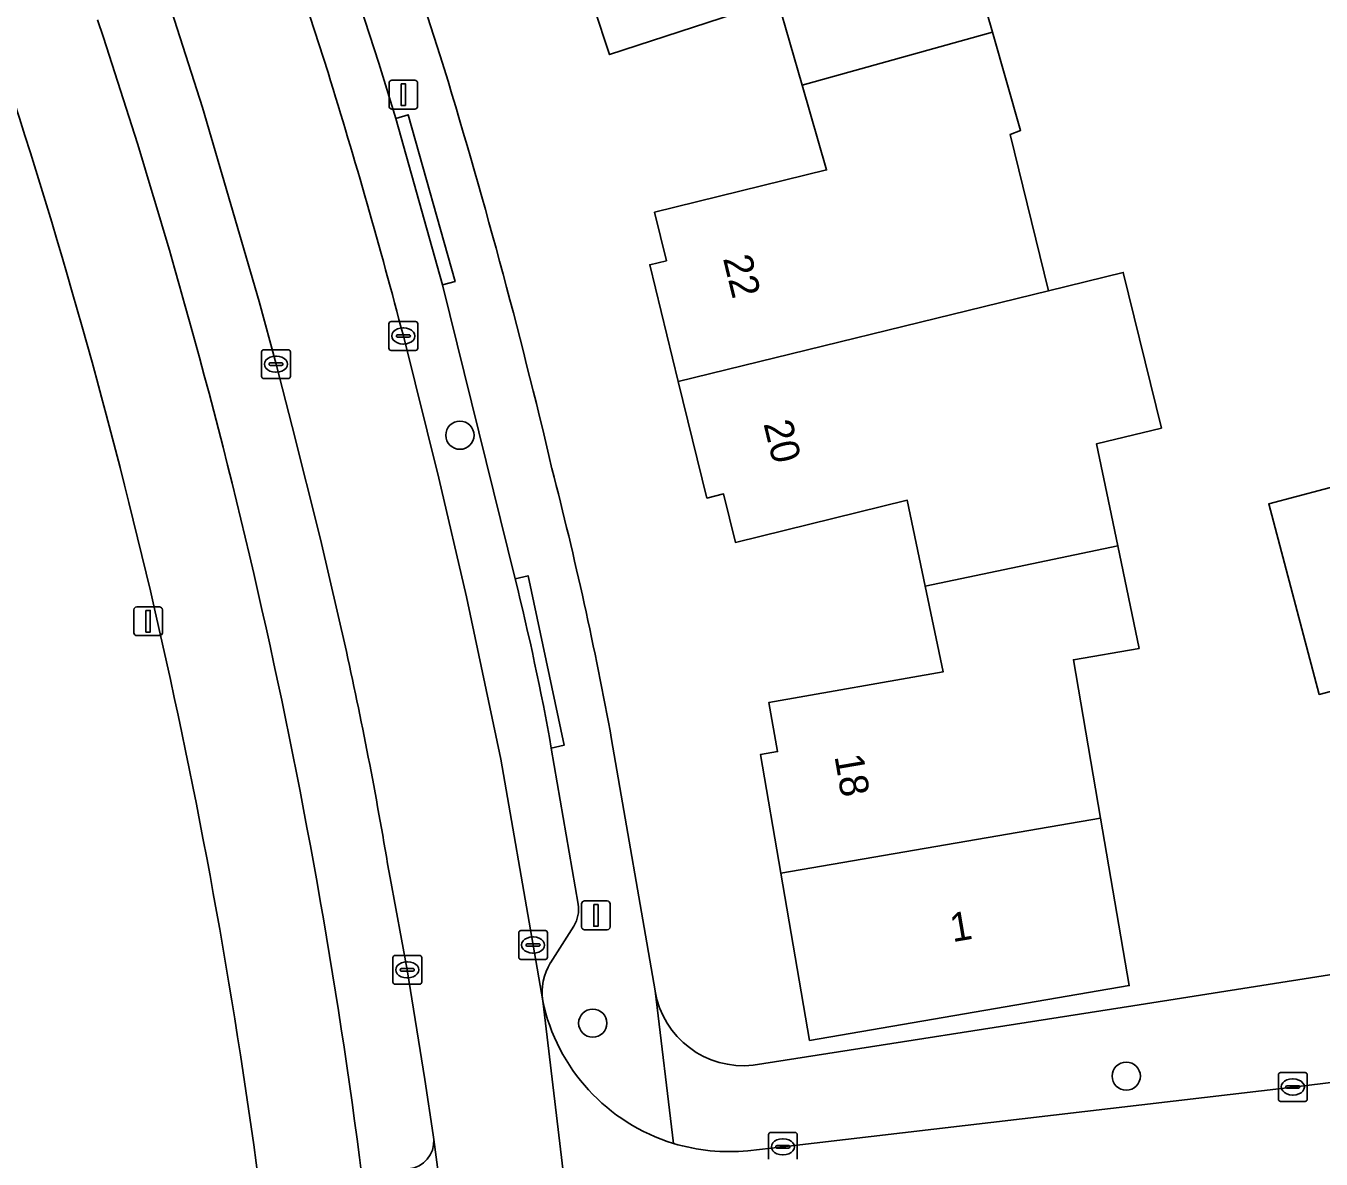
# Model space of a CAD drawing. Extents: x 162879 to 165540, y 384011 to 385181.
# Drawn here: x 163777.66 to 163822.64, y 384375.35 to 384414.7 of the extents above; entities that cross this region are included whole.
import ezdxf

# ---------------------------------------------------------------- set-up
doc = ezdxf.new("R2010")
doc.units = 0
for name, color, linetype in [('IMGEO_Boom', 7, 'Continuous'), ('IMGEO_Erf', 7, 'Continuous'), ('IMGEO_Fietspad_gesloten', 7, 'Continuous'), ('IMGEO_Groenvoorziening', 7, 'Continuous'), ('IMGEO_Kolk', 7, 'Continuous'), ('IMGEO_Lichtmast', 7, 'Continuous'), ('IMGEO_Muur', 7, 'Continuous'), ('IMGEO_Pand', 7, 'Continuous'), ('IMGEO_Pand_nummerreeks', 7, 'Continuous'), ('IMGEO_Parkeervlak_open', 7, 'Continuous'), ('IMGEO_Rijbaan_lokaal_open', 7, 'Continuous'), ('IMGEO_Voetpad_open', 7, 'Continuous')]:
    doc.layers.add(name, color=color, linetype=linetype)

msp = doc.modelspace()

# ---------------------------------------------------------------- linework, layer by layer
at = {"layer": 'IMGEO_Boom'}
for centre in [(163792.734, 384400.485), (163797.345, 384380.069), (163815.873, 384378.229)]:
    msp.add_circle(centre, 0.489, dxfattribs=at)
at = {"layer": 'IMGEO_Erf'}
for points in [[(163788.875, 384423.518), (163792.049, 384413.663)], [(163810.195, 384418.068), (163811.223, 384414.483), (163812.202, 384411.07), (163811.837, 384410.925), (163813.167, 384405.499), (163815.77, 384406.136), (163817.093, 384400.732), (163814.837, 384400.18), (163815.298, 384397.976), (163815.575, 384396.648), (163816.319, 384393.081), (163814.036, 384392.69), (163814.979, 384387.19), (163815.976, 384381.375), (163804.874, 384379.47), (163803.877, 384385.278), (163803.171, 384389.395), (163803.763, 384389.497), (163803.464, 384391.204), (163809.512, 384392.264), (163808.89, 384395.245), (163808.267, 384398.227), (163802.303, 384396.764), (163801.891, 384398.445), (163801.309, 384398.303), (163800.316, 384402.352), (163799.323, 384406.403), (163799.905, 384406.545), (163799.492, 384408.228), (163805.465, 384409.694), (163804.622, 384412.635), (163803.766, 384415.619), (163797.929, 384413.701), (163797.388, 384415.352)], [(163825.485, 384392.258), (163822.572, 384391.486), (163820.82, 384398.098), (163823.706, 384398.863)], [(163802.92, 384378.611), (163816.096, 384380.674), (163825.065, 384382.078), (163825.148, 384382.091), (163865.727, 384392.809)], [(163798.001, 384389.923), (163799.512, 384381.186)]]:
    msp.add_lwpolyline(points, dxfattribs=at)
for centre, radius, start, end in [((163583.354, 384349.501), 218.336, 13.19052, 17.08969), ((163667.151, 384366.009), 133.017, 10.35715, 14.5042), ((163802.573, 384381.694), 3.103, 189.4288, 276.4236)]:
    msp.add_arc(centre, radius, start, end, dxfattribs=at)
at = {"layer": 'IMGEO_Fietspad_gesloten'}
msp.add_lwpolyline([(163792.338, 384372.171), (163791.826, 384376.032)], dxfattribs=at)
for centre, radius, start, end in [((163578.641, 384347.699), 212.423, 7.31878, 18.44587), ((163573.957, 384346.303), 213.668, 7.60789, 18.44351), ((163790.862, 384375.972), 0.966, 275.5515, 3.5699)]:
    msp.add_arc(centre, radius, start, end, dxfattribs=at)
at = {"layer": 'IMGEO_Groenvoorziening'}
for points in [[(163788.792, 384392.978), (163787.888, 384396.88), (163786.914, 384400.782), (163786.348, 384402.953), (163785.764, 384405.127), (163783.795, 384411.861), (163780.97, 384420.679), (163779.798, 384424.262), (163779.007, 384426.681)], [(163791.826, 384376.032), (163791.802, 384376.197), (163791.512, 384378.112), (163790.907, 384381.92), (163790.306, 384385.111)]]:
    msp.add_lwpolyline(points, dxfattribs=at)
for centre, radius, start, end in [((163578.641, 384347.699), 212.423, 7.31878, 18.44587), ((163573.957, 384346.303), 213.668, 7.60789, 18.44351), ((163637.71, 384359.823), 154.677, 9.4094, 12.37732), ((163790.862, 384375.972), 0.966, 275.5515, 3.5699)]:
    msp.add_arc(centre, radius, start, end, dxfattribs=at)
at = {"layer": 'IMGEO_Kolk'}
for p, q in [((163790.269, 384403.504), (163790.269, 384404.356)), ((163790.344, 384404.43), (163791.196, 384404.43)), ((163790.757, 384404.21), (163790.782, 384404.21)), ((163791.27, 384404.356), (163791.27, 384403.504)), ((163790.528, 384403.924), (163790.528, 384403.936)), ((163790.966, 384403.887), (163790.568, 384403.887)), ((163790.571, 384403.973), (163790.969, 384403.973)), ((163791.012, 384403.936), (163791.012, 384403.924)), ((163785.846, 384402.527), (163785.846, 384403.379)), ((163785.921, 384403.453), (163786.773, 384403.453)), ((163786.847, 384403.379), (163786.847, 384402.527)), ((163791.196, 384403.43), (163790.344, 384403.43)), ((163790.78, 384403.65), (163790.755, 384403.65)), ((163786.105, 384402.947), (163786.105, 384402.959)), ((163786.543, 384402.91), (163786.145, 384402.91)), ((163786.148, 384402.996), (163786.546, 384402.996)), ((163786.334, 384403.233), (163786.359, 384403.233)), ((163786.589, 384402.959), (163786.589, 384402.947)), ((163786.773, 384402.453), (163785.921, 384402.453)), ((163786.357, 384402.673), (163786.332, 384402.673)), ((163794.774, 384382.356), (163794.774, 384383.208)), ((163794.849, 384383.282), (163795.701, 384383.282)), ((163795.262, 384383.062), (163795.287, 384383.062)), ((163795.775, 384383.208), (163795.775, 384382.356)), ((163795.033, 384382.776), (163795.033, 384382.788)), ((163795.471, 384382.739), (163795.073, 384382.739)), ((163795.076, 384382.825), (163795.474, 384382.825)), ((163795.517, 384382.788), (163795.517, 384382.776)), ((163790.405, 384381.494), (163790.405, 384382.346)), ((163790.48, 384382.42), (163791.332, 384382.42)), ((163790.893, 384382.2), (163790.918, 384382.2)), ((163791.406, 384382.346), (163791.406, 384381.494)), ((163795.701, 384382.282), (163794.849, 384382.282)), ((163795.285, 384382.502), (163795.26, 384382.502)), ((163790.664, 384381.914), (163790.664, 384381.926)), ((163791.102, 384381.877), (163790.704, 384381.877)), ((163790.707, 384381.963), (163791.105, 384381.963)), ((163791.148, 384381.926), (163791.148, 384381.914)), ((163791.332, 384381.42), (163790.48, 384381.42)), ((163790.916, 384381.64), (163790.891, 384381.64)), ((163821.155, 384377.427), (163821.155, 384378.279)), ((163821.23, 384378.353), (163822.082, 384378.353)), ((163821.643, 384378.133), (163821.668, 384378.133)), ((163822.156, 384378.279), (163822.156, 384377.427)), ((163821.414, 384377.847), (163821.414, 384377.859)), ((163821.852, 384377.81), (163821.454, 384377.81)), ((163821.457, 384377.896), (163821.855, 384377.896)), ((163821.898, 384377.859), (163821.898, 384377.847)), ((163822.082, 384377.353), (163821.23, 384377.353)), ((163821.666, 384377.573), (163821.641, 384377.573)), ((163803.448, 384375.349), (163803.448, 384376.201)), ((163803.523, 384376.275), (163804.375, 384376.275)), ((163803.936, 384376.055), (163803.961, 384376.055)), ((163804.449, 384376.201), (163804.449, 384375.349)), ((163803.707, 384375.769), (163803.707, 384375.781)), ((163804.145, 384375.732), (163803.747, 384375.732)), ((163803.75, 384375.818), (163804.148, 384375.818)), ((163803.959, 384375.495), (163803.934, 384375.495)), ((163804.191, 384375.781), (163804.191, 384375.769))]:
    msp.add_line(p, q, dxfattribs=at)
for points in [[(163790.269, 384403.504), (163790.269, 384404.356)], [(163790.344, 384404.43), (163791.196, 384404.43)], [(163791.27, 384404.356), (163791.27, 384403.504)], [(163785.846, 384402.527), (163785.846, 384403.379)], [(163785.921, 384403.453), (163786.773, 384403.453)], [(163786.847, 384403.379), (163786.847, 384402.527)], [(163791.196, 384403.43), (163790.344, 384403.43)], [(163786.773, 384402.453), (163785.921, 384402.453)], [(163794.774, 384382.356), (163794.774, 384383.208)], [(163794.849, 384383.282), (163795.701, 384383.282)], [(163795.775, 384383.208), (163795.775, 384382.356)], [(163790.405, 384381.494), (163790.405, 384382.346)], [(163790.48, 384382.42), (163791.332, 384382.42)], [(163791.406, 384382.346), (163791.406, 384381.494)], [(163795.701, 384382.282), (163794.849, 384382.282)], [(163791.332, 384381.42), (163790.48, 384381.42)], [(163821.155, 384377.427), (163821.155, 384378.279)], [(163821.23, 384378.353), (163822.082, 384378.353)], [(163822.156, 384378.279), (163822.156, 384377.427)], [(163822.082, 384377.353), (163821.23, 384377.353)], [(163803.448, 384375.349), (163803.448, 384376.201)], [(163803.523, 384376.275), (163804.375, 384376.275)], [(163804.449, 384376.201), (163804.449, 384375.349)]]:
    msp.add_lwpolyline(points, dxfattribs=at)
for centre, radius, start, end in [((163790.346, 384404.354), 0.0765, 91.552, 178.448), ((163790.346, 384404.354), 0.0765, 91.552, 178.448), ((163791.194, 384404.354), 0.0765, 1.552, 88.448), ((163791.194, 384404.354), 0.0765, 1.552, 88.448), ((163790.568, 384403.933), 0.0403, 85.8775, 175.7526), ((163790.565, 384403.923), 0.0366, 178.938, 274.7102), ((163790.969, 384403.93), 0.043, 264.8664, 352.4533), ((163790.973, 384403.935), 0.0386, 1.7309, 96.639), ((163785.923, 384403.377), 0.0765, 91.552, 178.448), ((163785.923, 384403.377), 0.0765, 91.552, 178.448), ((163786.771, 384403.377), 0.0765, 1.552, 88.448), ((163786.771, 384403.377), 0.0765, 1.552, 88.448), ((163790.346, 384403.506), 0.0765, 181.552, 268.448), ((163790.346, 384403.506), 0.0765, 181.552, 268.448), ((163791.194, 384403.506), 0.0765, 271.552, 358.448), ((163791.194, 384403.506), 0.0765, 271.552, 358.448), ((163786.145, 384402.956), 0.0403, 85.8775, 175.7526), ((163786.142, 384402.946), 0.0366, 178.938, 274.7102), ((163786.546, 384402.953), 0.043, 264.8664, 352.4533), ((163786.55, 384402.958), 0.0386, 1.7309, 96.639), ((163785.923, 384402.529), 0.0765, 181.552, 268.448), ((163785.923, 384402.529), 0.0765, 181.552, 268.448), ((163786.771, 384402.529), 0.0765, 271.552, 358.448), ((163786.771, 384402.529), 0.0765, 271.552, 358.448), ((163794.851, 384383.206), 0.0765, 91.552, 178.448), ((163794.851, 384383.206), 0.0765, 91.552, 178.448), ((163795.699, 384383.206), 0.0765, 1.552, 88.448), ((163795.699, 384383.206), 0.0765, 1.552, 88.448), ((163795.073, 384382.785), 0.0403, 85.8775, 175.7526), ((163795.07, 384382.775), 0.0366, 178.938, 274.7102), ((163795.474, 384382.782), 0.043, 264.8664, 352.4533), ((163795.478, 384382.787), 0.0386, 1.7309, 96.639), ((163790.482, 384382.344), 0.0765, 91.552, 178.448), ((163790.482, 384382.344), 0.0765, 91.552, 178.448), ((163791.33, 384382.344), 0.0765, 1.552, 88.448), ((163791.33, 384382.344), 0.0765, 1.552, 88.448), ((163794.851, 384382.358), 0.0765, 181.552, 268.448), ((163794.851, 384382.358), 0.0765, 181.552, 268.448), ((163795.699, 384382.358), 0.0765, 271.552, 358.448), ((163795.699, 384382.358), 0.0765, 271.552, 358.448), ((163790.704, 384381.923), 0.0403, 85.8775, 175.7526), ((163790.701, 384381.913), 0.0366, 178.938, 274.7102), ((163791.105, 384381.92), 0.043, 264.8664, 352.4533), ((163791.109, 384381.925), 0.0386, 1.7309, 96.639), ((163790.482, 384381.496), 0.0765, 181.552, 268.448), ((163790.482, 384381.496), 0.0765, 181.552, 268.448), ((163791.33, 384381.496), 0.0765, 271.552, 358.448), ((163791.33, 384381.496), 0.0765, 271.552, 358.448), ((163821.232, 384378.277), 0.0765, 91.552, 178.448), ((163821.232, 384378.277), 0.0765, 91.552, 178.448), ((163822.08, 384378.277), 0.0765, 1.552, 88.448), ((163822.08, 384378.277), 0.0765, 1.552, 88.448), ((163821.454, 384377.856), 0.0403, 85.8775, 175.7526), ((163821.451, 384377.846), 0.0366, 178.938, 274.7102), ((163821.855, 384377.853), 0.043, 264.8664, 352.4533), ((163821.859, 384377.858), 0.0386, 1.7309, 96.639), ((163821.232, 384377.429), 0.0765, 181.552, 268.448), ((163821.232, 384377.429), 0.0765, 181.552, 268.448), ((163822.08, 384377.429), 0.0765, 271.552, 358.448), ((163822.08, 384377.429), 0.0765, 271.552, 358.448), ((163803.525, 384376.199), 0.0765, 91.552, 178.448), ((163803.525, 384376.199), 0.0765, 91.552, 178.448), ((163804.373, 384376.199), 0.0765, 1.552, 88.448), ((163804.373, 384376.199), 0.0765, 1.552, 88.448), ((163803.747, 384375.778), 0.0403, 85.8775, 175.7526), ((163803.744, 384375.768), 0.0366, 178.938, 274.7102), ((163804.148, 384375.775), 0.043, 264.8664, 352.4533), ((163804.152, 384375.78), 0.0386, 1.7309, 96.639)]:
    msp.add_arc(centre, radius, start, end, dxfattribs=at)
for centre, major_axis, ratio, start_param, end_param in [((163790.756, 384403.93), (-0.387, 0.002), 0.722429, 4.712389, 7.853982), ((163790.781, 384403.93), (-0.39, 0.002), 0.717154, 1.570796, 4.712389), ((163786.333, 384402.953), (-0.387, 0.002), 0.722429, 4.712389, 7.853982), ((163786.358, 384402.953), (-0.39, 0.002), 0.717154, 1.570796, 4.712389), ((163795.261, 384382.782), (-0.387, 0.002), 0.722429, 4.712389, 7.853982), ((163795.286, 384382.782), (-0.39, 0.002), 0.717154, 1.570796, 4.712389), ((163790.892, 384381.92), (-0.387, 0.002), 0.722429, 4.712389, 7.853982), ((163790.917, 384381.92), (-0.39, 0.002), 0.717154, 1.570796, 4.712389), ((163821.642, 384377.853), (-0.387, 0.002), 0.722429, 4.712389, 7.853982), ((163821.667, 384377.853), (-0.39, 0.002), 0.717154, 1.570796, 4.712389), ((163803.935, 384375.775), (-0.387, 0.002), 0.722429, 4.712389, 7.853982), ((163803.96, 384375.775), (-0.39, 0.002), 0.717154, 1.570796, 4.712389)]:
    msp.add_ellipse(centre, major_axis=major_axis, ratio=ratio, start_param=start_param, end_param=end_param, dxfattribs=at)
at = {"layer": 'IMGEO_Lichtmast'}
for p, q in [((163790.373, 384412.811), (163791.163, 384412.811)), ((163791.163, 384412.811), (163790.373, 384412.811)), ((163790.273, 384411.911), (163790.273, 384412.711)), ((163790.273, 384412.711), (163790.273, 384411.911)), ((163791.263, 384412.711), (163791.263, 384411.911)), ((163791.263, 384411.911), (163791.263, 384412.711)), ((163791.163, 384411.811), (163790.373, 384411.811)), ((163790.373, 384411.811), (163791.163, 384411.811)), ((163781.412, 384393.625), (163781.412, 384394.425)), ((163781.412, 384394.425), (163781.412, 384393.625)), ((163781.512, 384394.525), (163782.302, 384394.525)), ((163782.302, 384394.525), (163781.512, 384394.525)), ((163782.402, 384394.425), (163782.402, 384393.625)), ((163782.402, 384393.625), (163782.402, 384394.425)), ((163782.302, 384393.525), (163781.512, 384393.525)), ((163781.512, 384393.525), (163782.302, 384393.525)), ((163796.96, 384383.412), (163796.96, 384384.212)), ((163796.96, 384384.212), (163796.96, 384383.412)), ((163797.06, 384384.312), (163797.85, 384384.312)), ((163797.85, 384384.312), (163797.06, 384384.312)), ((163797.95, 384384.212), (163797.95, 384383.412)), ((163797.95, 384383.412), (163797.95, 384384.212)), ((163797.85, 384383.312), (163797.06, 384383.312)), ((163797.06, 384383.312), (163797.85, 384383.312))]:
    msp.add_line(p, q, dxfattribs=at)
for points in [[(163790.693, 384412.686), (163790.843, 384412.686), (163790.843, 384411.936), (163790.693, 384411.936), (163790.693, 384412.686)], [(163781.832, 384394.4), (163781.982, 384394.4), (163781.982, 384393.65), (163781.832, 384393.65), (163781.832, 384394.4)], [(163797.38, 384384.187), (163797.53, 384384.187), (163797.53, 384383.437), (163797.38, 384383.437), (163797.38, 384384.187)]]:
    msp.add_lwpolyline(points, dxfattribs=at)
for centre, start, end in [((163790.373, 384412.711), 90, 180), ((163790.373, 384412.711), 90, 180), ((163791.163, 384412.711), 0, 90), ((163791.163, 384412.711), 360, 90), ((163790.373, 384411.911), 180, 270), ((163790.373, 384411.911), 180, 270), ((163791.163, 384411.911), 270, 0), ((163791.163, 384411.911), 270, 0), ((163781.512, 384394.425), 90, 180), ((163781.512, 384394.425), 90, 180), ((163782.302, 384394.425), 0, 90), ((163782.302, 384394.425), 360, 90), ((163781.512, 384393.625), 180, 270), ((163781.512, 384393.625), 180, 270), ((163782.302, 384393.625), 270, 0), ((163782.302, 384393.625), 270, 0), ((163797.06, 384384.212), 90, 180), ((163797.06, 384384.212), 90, 180), ((163797.85, 384384.212), 0, 90), ((163797.85, 384384.212), 360, 90), ((163797.06, 384383.412), 180, 270), ((163797.06, 384383.412), 180, 270), ((163797.85, 384383.412), 270, 0), ((163797.85, 384383.412), 270, 0)]:
    msp.add_arc(centre, 0.1, start, end, dxfattribs=at)
at = {"layer": 'IMGEO_Muur'}
msp.add_lwpolyline([(163816.096, 384380.674), (163825.065, 384382.078)], dxfattribs=at)
at = {"layer": 'IMGEO_Pand'}
for points in [[(163806.243, 384422.592), (163795.534, 384419.157), (163796.816, 384415.168), (163797.388, 384415.352), (163797.929, 384413.701), (163803.766, 384415.619), (163804.622, 384412.635), (163811.223, 384414.483), (163810.195, 384418.068), (163807.931, 384417.34)], [(163800.316, 384402.352), (163813.167, 384405.499), (163811.837, 384410.925), (163812.202, 384411.07), (163811.223, 384414.483), (163804.622, 384412.635), (163805.465, 384409.694), (163799.492, 384408.228), (163799.905, 384406.545), (163799.323, 384406.403)], [(163815.575, 384396.648), (163815.298, 384397.976), (163814.837, 384400.18), (163817.093, 384400.732), (163815.77, 384406.136), (163813.167, 384405.499), (163800.316, 384402.352), (163801.309, 384398.303), (163801.891, 384398.445), (163802.303, 384396.764), (163808.267, 384398.227), (163808.89, 384395.245)], [(163823.706, 384398.863), (163820.82, 384398.098), (163822.572, 384391.486), (163825.485, 384392.258)], [(163815.575, 384396.648), (163808.89, 384395.245), (163809.512, 384392.264), (163803.464, 384391.204), (163803.763, 384389.497), (163803.171, 384389.395), (163803.877, 384385.278), (163814.979, 384387.19), (163814.036, 384392.69), (163816.319, 384393.081)], [(163803.877, 384385.278), (163804.874, 384379.47), (163815.976, 384381.375), (163814.979, 384387.19)]]:
    msp.add_lwpolyline(points, close=True, dxfattribs=at)
at = {"layer": 'IMGEO_Parkeervlak_open'}
for points in [[(163785.209, 384422.153), (163786.091, 384419.455), (163788.156, 384413.074)], [(163794.65, 384395.502), (163792.131, 384405.702), (163790.509, 384411.482), (163789.922, 384413.4), (163787.826, 384419.852)], [(163790.769, 384403.93), (163792.001, 384398.994), (163792.968, 384394.876), (163794.151, 384389.233), (163795.273, 384382.782), (163795.608, 384380.841)], [(163796.842, 384384.196), (163795.908, 384389.617)], [(163795.879, 384382.169), (163796.694, 384383.441)]]:
    msp.add_lwpolyline(points, dxfattribs=at)
for centre, radius, start, end in [((163582.058, 384349.234), 215.759, 14.68506, 17.21069), ((163708.654, 384374.042), 88.633, 10.12067, 14.01166), ((163795.704, 384384.027), 1.151, 329.3832, 8.4351), ((163797.613, 384381.124), 2.025, 148.9105, 188.0219)]:
    msp.add_arc(centre, radius, start, end, dxfattribs=at)
at = {"layer": 'IMGEO_Rijbaan_lokaal_open'}
for points in [[(163785.005, 384423.713), (163782.356, 384431.947), (163777.69, 384430.711), (163779.007, 384426.681), (163779.798, 384424.262), (163780.97, 384420.679), (163783.795, 384411.861), (163785.764, 384405.127), (163786.348, 384402.953), (163786.914, 384400.782), (163787.888, 384396.88), (163788.792, 384392.978)], [(163788.156, 384413.074), (163786.091, 384419.455)], [(163793.942, 384348.009), (163793.966, 384342.761), (163794.029, 384323.01), (163794.044, 384316.879), (163794.053, 384313.108), (163794.058, 384311.269), (163798.545, 384311.271), (163798.527, 384321.799), (163798.524, 384322.125), (163798.524, 384322.164), (163798.514, 384323.297), (163798.442, 384342.795), (163798.415, 384349.126), (163798.161, 384356.538), (163797.966, 384359.207), (163797.641, 384363.843), (163795.608, 384380.841), (163795.273, 384382.782), (163794.151, 384389.233), (163792.968, 384394.876), (163792.001, 384398.994), (163790.769, 384403.93)], [(163868.168, 384389.455), (163865.713, 384388.799), (163834.844, 384380.604), (163826.557, 384378.434), (163823.263, 384378.046), (163821.656, 384377.851), (163803.948, 384375.773), (163802.736, 384375.641)], [(163790.306, 384385.111), (163790.907, 384381.92), (163791.512, 384378.112), (163791.802, 384376.197), (163791.826, 384376.032), (163792.338, 384372.171), (163793.045, 384364.945), (163793.524, 384358.981)], [(163795.608, 384380.841), (163797.641, 384363.843)]]:
    msp.add_lwpolyline(points, dxfattribs=at)
for centre, radius, start, end in [((163582.058, 384349.234), 215.759, 14.68506, 17.21069), ((163637.71, 384359.823), 154.677, 9.4094, 12.37732), ((163802.076, 384382.221), 6.614, 192.0418, 253.0316), ((163802.072, 384382.202), 6.594, 253.0186, 275.7793)]:
    msp.add_arc(centre, radius, start, end, dxfattribs=at)
at = {"layer": 'IMGEO_Voetpad_open'}
for points in [[(163792.049, 384413.663), (163788.875, 384423.518)], [(163787.826, 384419.852), (163789.922, 384413.4), (163790.509, 384411.482), (163790.939, 384411.614), (163792.567, 384405.819), (163792.131, 384405.702), (163794.65, 384395.502), (163795.101, 384395.605), (163796.348, 384389.718), (163795.908, 384389.617), (163796.842, 384384.196)], [(163795.908, 384389.617), (163796.348, 384389.718), (163795.101, 384395.605), (163794.65, 384395.502)], [(163865.727, 384392.809), (163825.148, 384382.091), (163825.065, 384382.078), (163816.096, 384380.674), (163802.92, 384378.611)], [(163800.146, 384375.895), (163799.512, 384381.186), (163798.001, 384389.923)], [(163796.694, 384383.441), (163795.879, 384382.169)], [(163799.512, 384381.186), (163800.146, 384375.895)], [(163802.736, 384375.641), (163803.948, 384375.773), (163821.656, 384377.851), (163823.263, 384378.046)]]:
    msp.add_lwpolyline(points, dxfattribs=at)
msp.add_lwpolyline([(163792.131, 384405.702), (163792.567, 384405.819), (163790.939, 384411.614), (163790.509, 384411.482)], close=True, dxfattribs=at)
for centre, radius, start, end in [((163583.354, 384349.501), 218.336, 13.19052, 17.08969), ((163667.151, 384366.009), 133.017, 10.35715, 14.5042), ((163708.654, 384374.042), 88.633, 10.12067, 14.01166), ((163795.704, 384384.027), 1.151, 329.3832, 8.4351), ((163797.613, 384381.124), 2.025, 148.9105, 188.0219), ((163802.076, 384382.221), 6.614, 192.0418, 253.0316), ((163802.573, 384381.694), 3.103, 189.4288, 276.4236), ((163802.072, 384382.202), 6.594, 253.0186, 275.7793)]:
    msp.add_arc(centre, radius, start, end, dxfattribs=at)

# ---------------------------------------------------------------- texts
at = {"layer": 'IMGEO_Pand_nummerreeks'}
for s, rotation, p in [('22', 283.7763, (163801.864, 384406.625)), ('20', 283.7763, (163803.27, 384400.887)), ('18', 279.7364, (163805.738, 384389.337)), ('1', 9.7366, (163809.84, 384382.879))]:
    msp.add_text(s, height=1, rotation=rotation, dxfattribs=at).set_placement(p)

doc.saveas('drawing.dxf')
